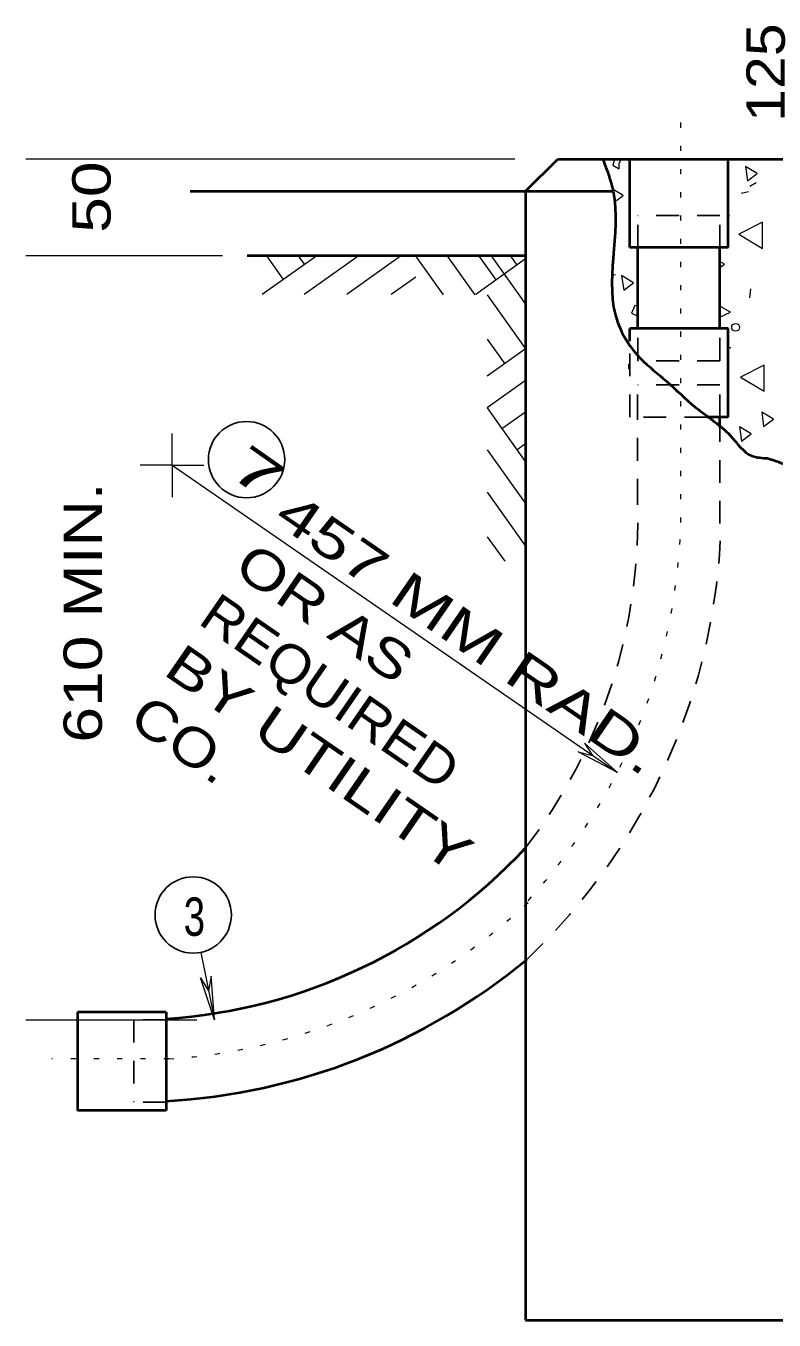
# Model space of a CAD drawing. Extents: x 312583 to 312854, y 144419 to 144597.
# Drawn here: x 312617.51 to 312632.33, y 144444 to 144469.64 of the extents above; entities that cross this region are included whole.
import ezdxf

# ---------------------------------------------------------------- set-up
doc = ezdxf.new("R2010")
doc.units = 0
doc.header["$LTSCALE"] = 0.3
doc.linetypes.add('DOTTED', pattern=[1.5, 0.3, -1.2])
doc.linetypes.add('SHORT_DASHED', pattern=[2.7, 1.5, -1.2])
doc.layers.add('1', color=7, linetype='Continuous', lineweight=25)
doc.layers.add('2', color=7, linetype='Continuous', lineweight=13)

msp = doc.modelspace()

# ---------------------------------------------------------------- linework, layer by layer
at = {"layer": '1', "linetype": 'DOTTED', "lineweight": 13}
for p, q in [((312630.478, 144459.8045), (312630.478, 144467.9465)), ((312620.335, 144449.1785), (312618.0196, 144449.1785))]:
    msp.add_line(p, q, dxfattribs=at)
at = {"layer": '1', "lineweight": 40}
for p, q in [((312627.4036, 144466.3672), (312628.04, 144467.0035)), ((312628.04, 144467.0035), (312653.6006, 144467.0035)), ((312629.466, 144465.2479), (312629.466, 144467.0035)), ((312631.4133, 144465.2479), (312631.4133, 144467.0035)), ((312620.7566, 144466.3672), (312629.1363, 144466.3672)), ((312627.4036, 144466.3672), (312627.4036, 144444.0035)), ((312627.4036, 144466.3672), (312629.1363, 144466.3672)), ((312631.4133, 144465.2479), (312629.466, 144465.2479)), ((312629.627, 144463.6455), (312629.627, 144465.2479)), ((312631.2523, 144463.6455), (312631.2523, 144465.2479)), ((312627.4036, 144465.0869), (312621.8913, 144465.0869)), ((312631.4133, 144463.6455), (312629.466, 144463.6455)), ((312629.466, 144463.3925), (312629.466, 144463.6455)), ((312631.4133, 144461.8899), (312631.4133, 144463.6455)), ((312631.4133, 144461.8899), (312630.9993, 144461.8899)), ((312631.2523, 144461.6905), (312631.2523, 144461.8899)), ((312620.2813, 144450.1062), (312618.5256, 144450.1062)), ((312618.5256, 144450.1062), (312618.5256, 144448.1589)), ((312620.2813, 144450.1062), (312620.2813, 144448.1589)), ((312620.2813, 144448.1589), (312618.5256, 144448.1589)), ((312627.4036, 144444.0035), (312654.237, 144444.0035))]:
    msp.add_line(p, q, dxfattribs=at)
at = {"layer": '1', "linetype": 'SHORT_DASHED'}
for p, q in [((312631.2523, 144465.8842), (312629.627, 144465.8842)), ((312629.627, 144465.2479), (312629.627, 144465.8842)), ((312631.2523, 144465.2479), (312631.2523, 144465.8842)), ((312629.627, 144463.0092), (312629.627, 144463.6455)), ((312631.2523, 144463.0092), (312631.2523, 144463.6455)), ((312631.2523, 144463.0092), (312629.627, 144463.0092)), ((312631.2523, 144462.5339), (312629.627, 144462.5339)), ((312631.2523, 144461.8899), (312631.2523, 144462.5339)), ((312631.2523, 144459.7815), (312631.2523, 144461.6905)), ((312619.645, 144449.9529), (312619.645, 144448.3199)), ((312620.2813, 144449.9529), (312619.645, 144449.9529)), ((312620.2813, 144448.3199), (312619.645, 144448.3199))]:
    msp.add_line(p, q, dxfattribs=at)
for points in [[(312630.9993, 144461.8899), (312629.466, 144461.8899), (312629.466, 144463.3925)], [(312629.6193, 144460.2185), (312629.6193, 144461.8899), (312629.6193, 144462.5339)]]:
    msp.add_lwpolyline(points, dxfattribs=at)
for centre, radius, start, end in [((312618.9422, 144459.8863), 10.6854, 322.35486, 1.79879), ((312618.9658, 144460.0946), 12.3146, 313.3975, 358.54034)]:
    msp.add_arc(centre, radius, start, end, dxfattribs=at)
at = {"layer": '1', "linetype": 'DOTTED', "lineweight": 13}
for centre, radius, start, end in [((312618.9658, 144460.0946), 11.516, 317.47812, 358.54081), ((312619.5766, 144460.6351), 11.484, 273.78312, 313.41877)]:
    msp.add_arc(centre, radius, start, end, dxfattribs=at)
at = {"layer": '1', "lineweight": 40}
for radius, start, end in [(10.6854, 273.78468, 317.09104), (12.3146, 273.28354, 309.60268)]:
    msp.add_arc((312619.5766, 144460.6351), radius, start, end, dxfattribs=at)
for points in [[(312628.937, 144466.9882), (312629.1363, 144466.3672), (312629.2283, 144463.7605), (312629.6806, 144463.0552), (312630.1943, 144462.6029), (312630.7616, 144462.0892), (312631.4593, 144461.5219), (312631.8886, 144461.1232), (312632.1953, 144461.0772)], [(312632.1953, 144461.0772), (312632.3333, 144461.0312), (312632.6553, 144460.9085), (312632.8776, 144460.8012), (312633.0616, 144460.6709), (312633.238, 144460.5329), (312633.4143, 144460.3489), (312633.4986, 144460.2262), (312633.5983, 144460.1342), (312633.6596, 144460.0805), (312633.7363, 144459.9655)]]:
    msp.add_spline(points, degree=3, dxfattribs=at)
at = {"layer": '2'}
for p, q in [((312627.189, 144467.0035), (312617.506, 144467.0035)), ((312629.259, 144466.9192), (312629.2973, 144466.9959)), ((312631.8426, 144466.4669), (312631.973, 144466.5359)), ((312631.674, 144466.3289), (312631.8196, 144466.3595)), ((312621.4006, 144465.0869), (312617.506, 144465.0869)), ((312622.1826, 144464.3279), (312623.2713, 144465.0945)), ((312622.2746, 144465.0869), (312622.6043, 144464.6192)), ((312622.8956, 144465.0869), (312623.0183, 144464.9182)), ((312623.0183, 144464.3279), (312624.061, 144465.0639)), ((312623.8616, 144464.3279), (312624.9273, 144465.0869)), ((312625.2263, 144465.0715), (312625.7706, 144464.3125)), ((312625.855, 144465.0715), (312626.3993, 144464.3125)), ((312626.4146, 144464.3279), (312627.4036, 144465.0332)), ((312626.4836, 144465.0715), (312626.8133, 144464.6115)), ((312626.7213, 144465.0869), (312627.4036, 144464.1285)), ((312627.1123, 144465.0715), (312627.2273, 144464.9029)), ((312629.144, 144464.7112), (312629.1823, 144464.7189)), ((312624.7433, 144464.3279), (312625.2263, 144464.6729)), ((312631.8426, 144464.2512), (312631.8656, 144464.4352)), ((312626.6446, 144464.3125), (312627.4036, 144463.2469)), ((312626.6446, 144463.4385), (312626.9896, 144462.9479)), ((312627.4036, 144463.2469), (312626.6446, 144462.7025)), ((312631.4133, 144463.2699), (312631.467, 144463.2699)), ((312629.4506, 144462.8405), (312629.4506, 144462.9479)), ((312627.4036, 144462.6182), (312626.6446, 144462.0739)), ((312626.6446, 144462.0739), (312627.4113, 144460.9929)), ((312627.4036, 144461.9895), (312626.936, 144461.6599)), ((312620.404, 144460.9392), (312620.404, 144461.5679)), ((312627.4036, 144461.3609), (312627.235, 144461.2459)), ((312626.6446, 144461.2459), (312627.3806, 144460.2032)), ((312620.404, 144460.9392), (312619.7676, 144460.9392)), ((312620.404, 144460.9392), (312629.2206, 144454.8519)), ((312620.404, 144460.9392), (312620.404, 144460.3029)), ((312620.404, 144460.9392), (312621.0326, 144460.9392)), ((312626.6446, 144460.4025), (312627.4036, 144459.3369)), ((312626.6446, 144459.5209), (312626.9896, 144459.0379)), ((312628.4463, 144455.2582), (312628.73, 144455.1892)), ((312629.2206, 144454.8519), (312628.4463, 144455.2582)), ((312628.569, 144455.4345), (312628.73, 144455.1892)), ((312629.2206, 144454.8519), (312628.569, 144455.4345)), ((312620.9713, 144451.2869), (312621.2396, 144449.9529)), ((312620.9636, 144450.7809), (312621.1246, 144450.5279)), ((312621.2396, 144449.9529), (312620.9636, 144450.7809)), ((312621.1783, 144450.8192), (312621.1246, 144450.5279)), ((312621.2396, 144449.9529), (312621.1783, 144450.8192)), ((312620.8946, 144449.9452), (312617.506, 144449.9452))]:
    msp.add_line(p, q, dxfattribs=at)
for points in [[(312629.167, 144466.9959), (312629.1286, 144466.8809), (312629.259, 144466.8119), (312629.259, 144466.9192)], [(312629.2053, 144466.1832), (312629.3356, 144466.2829), (312629.1363, 144466.3979)], [(312631.4133, 144465.8305), (312631.444, 144465.8842), (312631.4133, 144465.8919)], [(312631.2523, 144464.8569), (312631.3443, 144464.9182), (312631.2523, 144464.9719)], [(312629.627, 144464.0902), (312629.5656, 144464.1055), (312629.5043, 144463.9522), (312629.627, 144463.8909)], [(312631.2523, 144463.8679), (312631.4593, 144463.9675), (312631.2523, 144464.0902)]]:
    msp.add_lwpolyline(points, dxfattribs=at)
for points in [[(312631.7966, 144466.5742), (312631.9883, 144466.7199), (312631.7583, 144466.8579)], [(312632.0956, 144465.2325), (312632.0956, 144465.7539), (312631.628, 144465.5162)], [(312629.351, 144464.4045), (312629.5426, 144464.5502), (312629.305, 144464.6959)], [(312632.1263, 144462.4035), (312632.1263, 144462.9172), (312631.6586, 144462.6795)], [(312632.1186, 144461.7059), (312632.3103, 144461.8515), (312632.0803, 144461.9895)], [(312631.6816, 144461.4145), (312631.8733, 144461.5602), (312631.6433, 144461.6982)]]:
    msp.add_lwpolyline(points, close=True, dxfattribs=at)
msp.add_circle((312631.5636, 144463.6696), 0.0784, dxfattribs=at)
at = {"layer": '2', "lineweight": 25}
for centre in [(312621.876, 144461.0485), (312620.8199, 144452.0293)]:
    msp.add_circle(centre, 0.7557, dxfattribs=at)

# ---------------------------------------------------------------- texts
at = {"layer": '2'}
for s, rotation, width, p in [('125 ', 90, 1.15, (312632.538, 144467.7403)), ('50 ', 90, 1.25, (312619.184, 144465.5429)), ('7', 325, 1.7, (312621.4796, 144460.7654)), ('610 MIN.  ', 90, 1.25, (312619.0121, 144455.4445)), ('457 MM RAD.   ', 325.387, 1.4, (312622.385, 144459.8305)), ('OR AS', 325.4, 1.25, (312621.5846, 144458.8209)), ('REQUIRED', 325.4, 1.1, (312620.8918, 144457.8166)), ('BY UTILITY', 325.4, 1.3, (312620.199, 144456.8124)), ('CO.', 325.4, 1.2, (312619.5062, 144455.8082))]:
    msp.add_text(s, height=0.76, rotation=rotation, dxfattribs=dict(at, width=width)).set_placement(p)
at = {"layer": '2', "width": 0.75}
msp.add_text('3', height=0.76, dxfattribs=at).set_placement((312620.6313, 144451.6164))

doc.saveas('drawing.dxf')
